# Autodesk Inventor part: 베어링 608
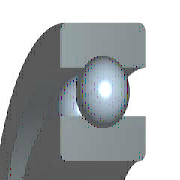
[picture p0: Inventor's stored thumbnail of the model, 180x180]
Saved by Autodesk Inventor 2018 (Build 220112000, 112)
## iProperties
IsCustomPart: 1
Created: 2012-02
Part Number: 베어링 608
Material: 강철, 연강
Description: 깊은 그루브 볼 베어링
Document SubType Name: Modeling
Standard: KS B 2023
Designer: mduedu
Standards Organization: KS
Language: ko-KR
Size Designation: 608 - 8 x 22 x 7
Categories: <MemberInstance><Categories><Category DisplayName="샤프트 부품" InternalName="7f7aeb1f-a693-4053-b835-cee3144e0d98" Mnemonic="SHFT"><Category DisplayName="베어링" Inter
Density: 1 g/cm^3
Appearance: 노란색
Author: mduedu
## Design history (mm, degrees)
sketch "스케치" dims "d0" = 3.64 (= -0.26 x WD + 0.26 x BD)
  geometry: L1 (1.68, 7.5)-(5.32, 7.5); L2 (3.5, 7.5)-(3.5, 5.68); L3 (3.5, 7.5)-(3.5, 9.32); L4 (2.148, 6.282)-(0, 6.282); L5 (0, 4)-(7, 4); L6 (2.148, 8.718)-(0, 8.718); L7 (0, 11)-(7, 11); L8 (7, 4)-(7, 6.282); L9 (4.852, 6.282)-(7, 6.282); L10 (4.852, 8.718)-(7, 8.718); L11 (7, 11)-(7, 8.718); L12 (-1.4, 0)-(8.4, 0) reference; L13 (0, -0.3)-(0, 5.3) reference
  constraints: 22 end point, 4 point on line, 2 collinear, 2 perpendicular, 2 symmetric about line, 1 midpoint, 1 parallel, 14 other
  dimensions: "d9" = 8 diameter of L5 L12 (= WD); "d11" = 22 diameter of L7 L12 (= BD); "d12" = 7 distance between parallel lines of L8 L13 (= KB); "d13" = 12.564 diameter of L9 L12 (= 0.326 x BD + 0.674 x WD)
revolve "본체" stored, may be unused: angle "d6" = 90 deg
revolve "볼" stored, may be unused: angle "d7" = 90 deg
pattern_circular "IDS_ARRAYBALL[SIMPL:T]" dims angle "d3" = 360 deg
body "Solid1"
fillet "모깎기1" dims "d1" = 0.3 (= KRS)
other parameters: "WD" = 8 [user parameter; used in 5 equation terms], "BD" = 22 [user parameter; used in 5 equation terms], "KB" = 7 [user parameter; used in 1 equation term], "KRS" = 0.3 [user parameter; used in 1 equation term], "d4" = 0, "d5" = 0, "d8" = 0, "d14" = 0, "d15" = 0, "BBA" = 0 [user parameter], "BC0" = 1370000 [user parameter], "BC" = 3250000 [user parameter], "BR" = 11 (= 0.5 x BD) [user parameter], "WR" = 4 (= 0.5 x WD) [user parameter]
